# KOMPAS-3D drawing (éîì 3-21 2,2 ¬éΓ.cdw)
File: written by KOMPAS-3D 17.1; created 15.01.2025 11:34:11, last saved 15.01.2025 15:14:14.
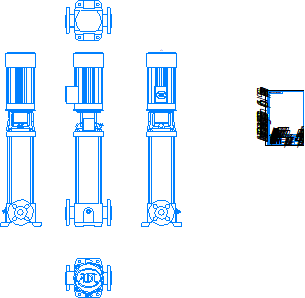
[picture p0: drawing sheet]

Sheet 1: A4, portrait

Title block, sheet 1: name: ВМН 3-21 2,2 кВт; designation: ВМН 3-21 2,2 кВт; material: Сталь 10  ГОСТ 1050-2013; mass: 68,16; sheets: 1; sheet format: A4; stored path: \\adlc.lan\data\АДЛ_ПКД\3D-модели\ADL production\Насосы ГРАНПАМП\Насосы ВМН\ВМН3\KOMPAS 3D\ВМН 3-21 2,2 кВт.cdw

Views: Проекционный вид 2, Проекционный вид 3, Проекционный вид 4, Проекционный вид 5
Referenced files in \\adlc.lan\data\АДЛ_ПКД\3D-модели\ADL production\Насосы ГРАНПАМП\Насосы ВМН\ВМН3\KOMPAS 3D\: ВМН 3-21 2,2 кВт.m3d
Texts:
  Andrey
  АДЛ
Dimensions and other numbers on the sheet: 1:1; 1; 68,16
